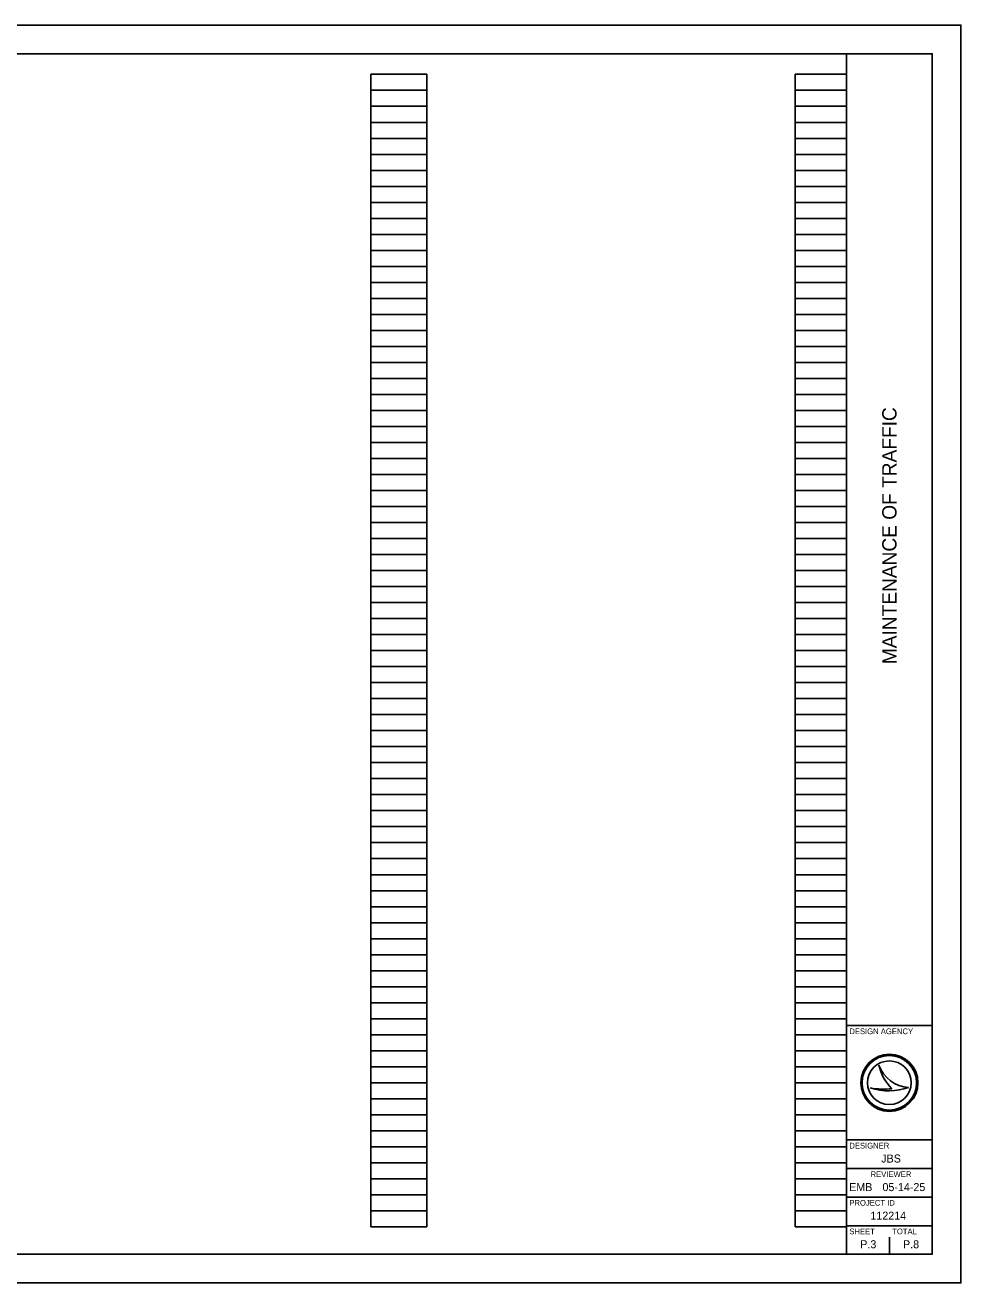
# Model space of a CAD drawing. Extents: x 0 to 34, y 0 to 22.
# Drawn here: x 17.63 to 34, y 0 to 22 of the extents above; entities that cross this region are included whole.
import ezdxf

# ---------------------------------------------------------------- set-up
doc = ezdxf.new("R2010")
doc.units = 0
for name, color, linetype in [('SH_Border', 7, 'Continuous'), ('SH_Cut_Line', 7, 'Continuous'), ('SH_Data', 7, 'Continuous')]:
    doc.layers.add(name, color=color, linetype=linetype)

msp = doc.modelspace()

# ---------------------------------------------------------------- linework, layer by layer
at = {"layer": 'SH_Border'}
for p, q in [((32, 0.5), (32, 21.5)), ((32, 4.5), (33.5, 4.5)), ((32, 2.5), (33.5, 2.5)), ((32, 2), (33.5, 2)), ((32, 1.5), (33.5, 1.5)), ((32, 1), (33.5, 1))]:
    msp.add_line(p, q, dxfattribs=at)
msp.add_lwpolyline([(1.5, 21.5), (33.5, 21.5), (33.5, 0.5), (1.5, 0.5)], close=True, dxfattribs=at)
at = {"layer": 'SH_Cut_Line'}
msp.add_lwpolyline([(0, 0), (34, 0), (34, 22), (0, 22)], close=True, dxfattribs=at)
at = {"layer": 'SH_Data'}
for p, q in [((23.68, 0.98), (23.68, 21.14)), ((23.68, 21.14), (24.66, 21.14)), ((24.66, 0.98), (24.66, 21.14)), ((31.1, 0.98), (31.1, 21.14)), ((31.1, 21.14), (32, 21.14)), ((32, 0.98), (32, 21.14)), ((23.68, 20.86), (24.66, 20.86)), ((31.1, 20.86), (32, 20.86)), ((23.68, 20.58), (24.66, 20.58)), ((31.1, 20.58), (32, 20.58)), ((23.68, 20.3), (24.66, 20.3)), ((31.1, 20.3), (32, 20.3)), ((23.68, 20.02), (24.66, 20.02)), ((31.1, 20.02), (32, 20.02)), ((23.68, 19.74), (24.66, 19.74)), ((31.1, 19.74), (32, 19.74)), ((23.68, 19.46), (24.66, 19.46)), ((31.1, 19.46), (32, 19.46)), ((23.68, 19.18), (24.66, 19.18)), ((31.1, 19.18), (32, 19.18)), ((23.68, 18.9), (24.66, 18.9)), ((31.1, 18.9), (32, 18.9)), ((23.68, 18.62), (24.66, 18.62)), ((31.1, 18.62), (32, 18.62)), ((23.68, 18.34), (24.66, 18.34)), ((31.1, 18.34), (32, 18.34)), ((23.68, 18.06), (24.66, 18.06)), ((31.1, 18.06), (32, 18.06)), ((23.68, 17.78), (24.66, 17.78)), ((31.1, 17.78), (32, 17.78)), ((23.68, 17.5), (24.66, 17.5)), ((31.1, 17.5), (32, 17.5)), ((23.68, 17.22), (24.66, 17.22)), ((31.1, 17.22), (32, 17.22)), ((23.68, 16.94), (24.66, 16.94)), ((31.1, 16.94), (32, 16.94)), ((23.68, 16.66), (24.66, 16.66)), ((31.1, 16.66), (32, 16.66)), ((23.68, 16.38), (24.66, 16.38)), ((31.1, 16.38), (32, 16.38)), ((23.68, 16.1), (24.66, 16.1)), ((31.1, 16.1), (32, 16.1)), ((23.68, 15.82), (24.66, 15.82)), ((31.1, 15.82), (32, 15.82)), ((23.68, 15.54), (24.66, 15.54)), ((31.1, 15.54), (32, 15.54)), ((23.68, 15.26), (24.66, 15.26)), ((31.1, 15.26), (32, 15.26)), ((23.68, 14.98), (24.66, 14.98)), ((31.1, 14.98), (32, 14.98)), ((23.68, 14.7), (24.66, 14.7)), ((31.1, 14.7), (32, 14.7)), ((23.68, 14.42), (24.66, 14.42)), ((31.1, 14.42), (32, 14.42)), ((23.68, 14.14), (24.66, 14.14)), ((31.1, 14.14), (32, 14.14)), ((23.68, 13.86), (24.66, 13.86)), ((31.1, 13.86), (32, 13.86)), ((23.68, 13.58), (24.66, 13.58)), ((31.1, 13.58), (32, 13.58)), ((23.68, 13.3), (24.66, 13.3)), ((31.1, 13.3), (32, 13.3)), ((23.68, 13.02), (24.66, 13.02)), ((31.1, 13.02), (32, 13.02)), ((23.68, 12.74), (24.66, 12.74)), ((31.1, 12.74), (32, 12.74)), ((23.68, 12.46), (24.66, 12.46)), ((31.1, 12.46), (32, 12.46)), ((23.68, 12.18), (24.66, 12.18)), ((31.1, 12.18), (32, 12.18)), ((23.68, 11.9), (24.66, 11.9)), ((31.1, 11.9), (32, 11.9)), ((23.68, 11.62), (24.66, 11.62)), ((31.1, 11.62), (32, 11.62)), ((23.68, 11.34), (24.66, 11.34)), ((31.1, 11.34), (32, 11.34)), ((23.68, 11.06), (24.66, 11.06)), ((31.1, 11.06), (32, 11.06)), ((23.68, 10.78), (24.66, 10.78)), ((31.1, 10.78), (32, 10.78)), ((23.68, 10.5), (24.66, 10.5)), ((31.1, 10.5), (32, 10.5)), ((23.68, 10.22), (24.66, 10.22)), ((31.1, 10.22), (32, 10.22)), ((23.68, 9.94), (24.66, 9.94)), ((31.1, 9.94), (32, 9.94)), ((23.68, 9.66), (24.66, 9.66)), ((31.1, 9.66), (32, 9.66)), ((23.68, 9.38), (24.66, 9.38)), ((31.1, 9.38), (32, 9.38)), ((23.68, 9.1), (24.66, 9.1)), ((31.1, 9.1), (32, 9.1)), ((23.68, 8.82), (24.66, 8.82)), ((31.1, 8.82), (32, 8.82)), ((23.68, 8.54), (24.66, 8.54)), ((31.1, 8.54), (32, 8.54)), ((23.68, 8.26), (24.66, 8.26)), ((31.1, 8.26), (32, 8.26)), ((23.68, 7.98), (24.66, 7.98)), ((31.1, 7.98), (32, 7.98)), ((23.68, 7.7), (24.66, 7.7)), ((31.1, 7.7), (32, 7.7)), ((23.68, 7.42), (24.66, 7.42)), ((31.1, 7.42), (32, 7.42)), ((23.68, 7.14), (24.66, 7.14)), ((31.1, 7.14), (32, 7.14)), ((23.68, 6.86), (24.66, 6.86)), ((31.1, 6.86), (32, 6.86)), ((23.68, 6.58), (24.66, 6.58)), ((31.1, 6.58), (32, 6.58)), ((23.68, 6.3), (24.66, 6.3)), ((31.1, 6.3), (32, 6.3)), ((23.68, 6.02), (24.66, 6.02)), ((31.1, 6.02), (32, 6.02)), ((23.68, 5.74), (24.66, 5.74)), ((31.1, 5.74), (32, 5.74)), ((23.68, 5.46), (24.66, 5.46)), ((31.1, 5.46), (32, 5.46)), ((23.68, 5.18), (24.66, 5.18)), ((31.1, 5.18), (32, 5.18)), ((23.68, 4.9), (24.66, 4.9)), ((31.1, 4.9), (32, 4.9)), ((23.68, 4.62), (24.66, 4.62)), ((31.1, 4.62), (32, 4.62)), ((23.68, 4.34), (24.66, 4.34)), ((31.1, 4.34), (32, 4.34)), ((23.68, 4.06), (24.66, 4.06)), ((31.1, 4.06), (32, 4.06)), ((23.68, 3.78), (24.66, 3.78)), ((31.1, 3.78), (32, 3.78)), ((32.567, 3.81), (32.567, 3.81)), ((23.68, 3.5), (24.66, 3.5)), ((31.1, 3.5), (32, 3.5)), ((32.417, 3.41), (32.417, 3.41)), ((32.75, 3.5), (32.75, 3.5)), ((33.087, 3.419), (33.087, 3.419)), ((23.68, 3.22), (24.66, 3.22)), ((31.1, 3.22), (32, 3.22)), ((23.68, 2.94), (24.66, 2.94)), ((31.1, 2.94), (32, 2.94)), ((23.68, 2.66), (24.66, 2.66)), ((31.1, 2.66), (32, 2.66)), ((23.68, 2.38), (24.66, 2.38)), ((31.1, 2.38), (32, 2.38)), ((23.68, 2.1), (24.66, 2.1)), ((31.1, 2.1), (32, 2.1)), ((23.68, 1.82), (24.66, 1.82)), ((31.1, 1.82), (32, 1.82)), ((23.68, 1.54), (24.66, 1.54)), ((31.1, 1.54), (32, 1.54)), ((23.68, 1.26), (24.66, 1.26)), ((31.1, 1.26), (32, 1.26)), ((23.68, 0.98), (24.66, 0.98)), ((31.1, 0.98), (32, 0.98)), ((32.375, 0.675), (32.375, 0.675)), ((32.75, 0.5), (32.75, 0.8))]:
    msp.add_line(p, q, dxfattribs=at)
for radius in [0.5, 0.477, 0.477, 0.382]:
    msp.add_circle((32.75, 3.5), radius, dxfattribs=at)
for centre, radius, start, end in [((33.116, 3.998), 0.58, 198.9257, 198.9319), ((33.347, 3.97), 0.796, 191.6379, 191.6421), ((33.116, 3.998), 0.58, 198.9319, 267.1657), ((33.347, 3.97), 0.796, 191.6421, 226.0947), ((32.739, 4.37), 1.013, 251.4576, 290.0832), ((32.648, 4.654), 1.266, 259.4964, 259.4995), ((32.739, 4.37), 1.013, 251.4527, 251.4576), ((32.648, 4.654), 1.266, 259.4995, 276.6672)]:
    msp.add_arc(centre, radius, start, end, dxfattribs=at)

# ---------------------------------------------------------------- texts
msp.add_text('MAINTENANCE OF TRAFFIC', height=0.25, rotation=90, dxfattribs=at).set_placement((32.875, 10.822))
for s, height, p in [('DESIGN AGENCY', 0.1, (32.05, 4.35)), ('DESIGNER', 0.1, (32.05, 2.35)), ('JBS', 0.14, (32.608, 2.105)), ('REVIEWER', 0.1, (32.422, 1.85)), ('EMB', 0.14, (32.047, 1.605)), ('05-14-25', 0.14, (32.629, 1.605)), ('PROJECT ID', 0.1, (32.05, 1.35)), ('112214', 0.14, (32.418, 1.105)), ('SHEET', 0.1, (32.05, 0.85)), ('TOTAL', 0.1, (32.8, 0.85)), ('P.3', 0.14, (32.241, 0.605)), ('P.8', 0.14, (32.989, 0.605))]:
    msp.add_text(s, height=height, dxfattribs=at).set_placement(p)

doc.saveas('drawing.dxf')
